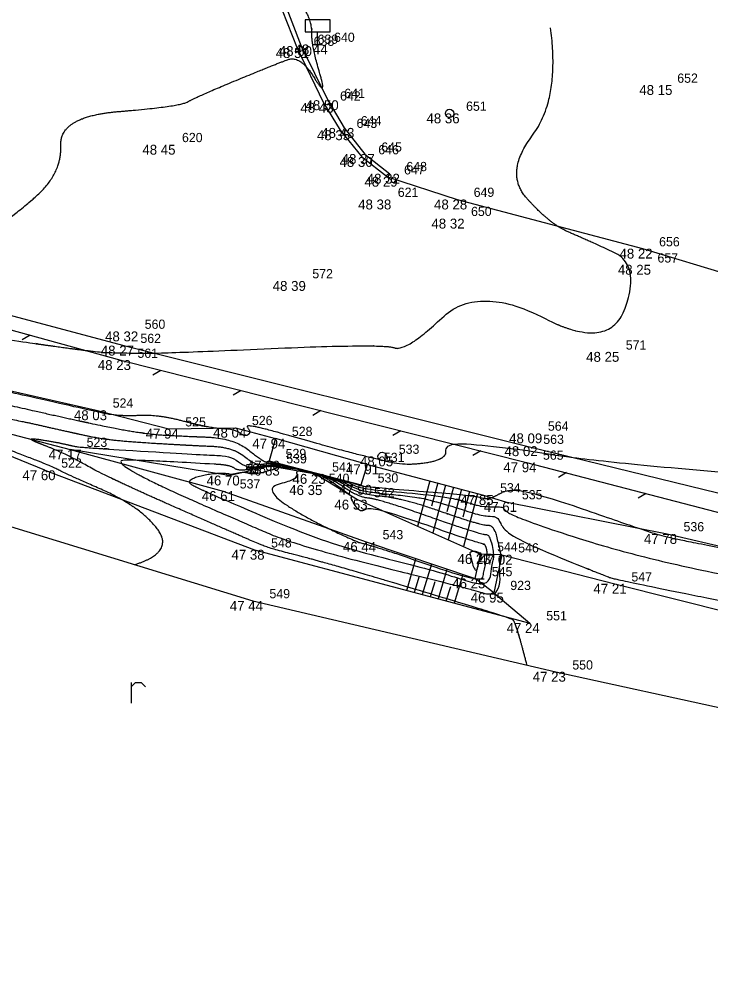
# Model space of a CAD drawing. Extents: x -704017 to -701500, y -1008977 to -1008450.
# Drawn here: x -703689.28 to -703668.32, y -1008728.25 to -1008699.18 of the extents above; entities that cross this region are included whole.
import ezdxf

# ---------------------------------------------------------------- set-up
doc = ezdxf.new("R2010")
doc.units = 0
for name, color, linetype in [('Z_bet_konstrukce', 7, 'Continuous'), ('Z_body', 7, 'Continuous'), ('Z_body_cisla', 7, 'Continuous'), ('Z_body_vysky', 7, 'Continuous'), ('Z_dopravni_znaceni', 7, 'Continuous'), ('Z_komunikace', 7, 'Continuous'), ('Z_obruby', 7, 'Continuous'), ('Z_popis', 7, 'Continuous'), ('Z_rozhrani_nezpevnene', 7, 'Continuous'), ('Z_site_znaky_plynovod', 7, 'Continuous'), ('Z_sloupky', 7, 'Continuous'), ('Z_svodidla', 7, 'Continuous'), ('Z_teren_hrany_paty', 7, 'Continuous'), ('Z_vrstevnice_hlavni', 7, 'Continuous'), ('Z_vrstevnice_vedlejsi', 7, 'Continuous')]:
    doc.layers.add(name, color=color, linetype=linetype)

# ---------------------------------------------------------------- blocks, each defined once
blk = doc.blocks.new('POINT_DISPLAY')
blk.add_line((0, 0), (0, 0))
blk = doc.blocks.new('Z529')
blk.add_line((0, 0), (0.2, 0.2))
blk = doc.blocks.new('Z301')
for p, q in [((-0.13, 0.38), (-0.13, -0.25)), ((-0.13, 0.25), (0, 0.38)), ((0, 0.38), (0.17, 0.38)), ((0.17, 0.38), (0.3, 0.25))]:
    blk.add_line(p, q)
blk = doc.blocks.new('Z526')
for p, q in [((0.38, 0.75), (-0.38, 0.75)), ((-0.38, 0.75), (-0.38, 0.38)), ((0.38, 0.38), (0.38, 0.75)), ((-0.38, 0.38), (0.38, 0.38)), ((0, 0), (0, 0.38)), ((-0.13, 0), (0.13, 0))]:
    blk.add_line(p, q)
blk = doc.blocks.new('Z15')
blk.add_circle((0, 0), 0.125)
blk = doc.blocks.new('Z614')
for p, q in [((-0.13, 0.03), (-0.1, 0.08)), ((-0.13, -0.03), (-0.13, 0.03)), ((-0.1, 0.08), (-0.08, 0.1)), ((-0.08, 0.1), (-0.03, 0.13)), ((-0.03, 0.13), (0.03, 0.13)), ((0.03, 0.13), (0.08, 0.1)), ((0.08, 0.1), (0.1, 0.08)), ((0.1, 0.08), (0.13, 0.03)), ((0.13, 0.03), (0.13, -0.03)), ((-0.1, -0.08), (-0.13, -0.03)), ((-0.08, -0.1), (-0.1, -0.08)), ((-0.03, -0.13), (-0.08, -0.1)), ((0.03, -0.13), (-0.03, -0.13)), ((0.08, -0.1), (0.03, -0.13)), ((0.1, -0.08), (0.08, -0.1)), ((0.13, -0.03), (0.1, -0.08))]:
    blk.add_line(p, q)

msp = doc.modelspace()

# ---------------------------------------------------------------- linework, layer by layer
at = {"layer": 'Z_bet_konstrukce'}
for p, q in [((-703681.52, -1008711.9), (-703681.71, -1008712.57)), ((-703678.73, -1008712.68), (-703681.52, -1008711.9)), ((-703681.71, -1008712.57), (-703678.92, -1008713.3)), ((-703678.92, -1008713.3), (-703678.73, -1008712.68))]:
    msp.add_line(p, q, dxfattribs=at)
at = {"layer": 'Z_komunikace'}
for p, q in [((-703681.66, -1008698.04), (-703680.86, -1008700.06)), ((-703680.86, -1008700.06), (-703680.06, -1008701.72)), ((-703680.06, -1008701.72), (-703679.56, -1008702.55)), ((-703679.56, -1008702.55), (-703678.9, -1008703.36)), ((-703678.9, -1008703.36), (-703678.12, -1008703.96)), ((-703678.12, -1008703.96), (-703676.01, -1008704.65)), ((-703676.01, -1008704.65), (-703670.39, -1008706.14)), ((-703670.39, -1008706.14), (-703661.94, -1008708.7)), ((-703694.9, -1008706.74), (-703686.11, -1008709.08)), ((-703686.11, -1008709.08), (-703673.9, -1008712.13)), ((-703673.9, -1008712.13), (-703663.52, -1008714.67))]:
    msp.add_line(p, q, dxfattribs=at)
at = {"layer": 'Z_obruby'}
for p, q in [((-703681.52, -1008697.96), (-703680.74, -1008700)), ((-703680.74, -1008700), (-703679.93, -1008701.64)), ((-703679.93, -1008701.64), (-703679.43, -1008702.48)), ((-703679.43, -1008702.48), (-703678.81, -1008703.27)), ((-703678.81, -1008703.27), (-703678.05, -1008703.87)), ((-703678.05, -1008703.87), (-703678.12, -1008703.96))]:
    msp.add_line(p, q, dxfattribs=at)
at = {"layer": 'Z_rozhrani_nezpevnene'}
for p, q in [((-703691.76, -1008713.89), (-703682.2, -1008716.82)), ((-703682.2, -1008716.82), (-703673.02, -1008718.97)), ((-703673.02, -1008718.97), (-703649.06, -1008724.21))]:
    msp.add_line(p, q, dxfattribs=at)
at = {"layer": 'Z_svodidla'}
for p, q in [((-703694.98, -1008707.1), (-703686.2, -1008709.52)), ((-703686.2, -1008709.52), (-703673.91, -1008712.62)), ((-703673.91, -1008712.62), (-703663.57, -1008715.31))]:
    msp.add_line(p, q, dxfattribs=at)
at = {"layer": 'Z_teren_hrany_paty'}
for p, q in [((-703693.42, -1008709.56), (-703686.95, -1008711.04)), ((-703693.92, -1008710.62), (-703687.74, -1008712.23)), ((-703688.51, -1008712.86), (-703693.92, -1008710.62)), ((-703686.95, -1008711.04), (-703684.75, -1008711.6)), ((-703684.75, -1008711.6), (-703682.73, -1008711.57)), ((-703682.73, -1008711.57), (-703681.52, -1008711.9)), ((-703687.74, -1008712.23), (-703683.1, -1008713.49)), ((-703682.93, -1008713.02), (-703687.74, -1008712.23)), ((-703682.93, -1008713.02), (-703681.69, -1008712.72)), ((-703681.69, -1008712.72), (-703680.3, -1008712.97)), ((-703678.73, -1008712.68), (-703675.21, -1008713.61)), ((-703688.51, -1008712.86), (-703682.15, -1008715.27)), ((-703680.3, -1008712.97), (-703679.03, -1008713.75)), ((-703676.84, -1008713.18), (-703677.21, -1008714.56)), ((-703676.6, -1008713.24), (-703676.79, -1008713.95)), ((-703676.36, -1008713.31), (-703676.75, -1008714.76)), ((-703683.1, -1008713.49), (-703678.77, -1008715.03)), ((-703676.12, -1008713.37), (-703676.32, -1008714.12)), ((-703675.88, -1008713.43), (-703676.28, -1008714.97)), ((-703675.64, -1008713.5), (-703675.84, -1008714.28)), ((-703675.39, -1008713.56), (-703675.82, -1008715.17)), ((-703675.21, -1008713.61), (-703674.55, -1008713.82)), ((-703679.03, -1008713.75), (-703675.3, -1008715.4)), ((-703674.55, -1008713.82), (-703669.65, -1008714.79)), ((-703669.65, -1008714.79), (-703648.46, -1008719.69)), ((-703678.77, -1008715.03), (-703675.46, -1008716.14)), ((-703682.15, -1008715.27), (-703673.81, -1008717.49)), ((-703675.46, -1008716.14), (-703675.3, -1008715.4)), ((-703674.66, -1008715.42), (-703675.3, -1008715.4)), ((-703677.54, -1008716.5), (-703677.26, -1008715.54)), ((-703674.66, -1008715.42), (-703674.9, -1008716.57)), ((-703674.66, -1008715.42), (-703671.23, -1008716.3)), ((-703677.06, -1008716.62), (-703676.78, -1008715.7)), ((-703676.58, -1008716.75), (-703676.31, -1008715.86)), ((-703677.3, -1008716.56), (-703677.16, -1008716.09)), ((-703676.82, -1008716.69), (-703676.68, -1008716.23)), ((-703676.09, -1008716.88), (-703675.83, -1008716.01)), ((-703674.9, -1008716.57), (-703675.46, -1008716.14)), ((-703676.34, -1008716.82), (-703676.2, -1008716.38)), ((-703671.23, -1008716.3), (-703648.67, -1008721.98)), ((-703674.9, -1008716.57), (-703673.81, -1008717.49))]:
    msp.add_line(p, q, dxfattribs=at)
at = {"layer": 'Z_vrstevnice_hlavni'}
for points in [[(-703662.375, -1008703.261), (-703663.705, -1008704.538), (-703663.066, -1008706.616), (-703661.034, -1008707.71), (-703652.649, -1008710.765), (-703650.692, -1008713.756), (-703662.914, -1008712.66), (-703663.337, -1008713.482), (-703663.459, -1008713.218), (-703665.771, -1008713.127), (-703672.17, -1008712.553), (-703673.902, -1008712.253), (-703676.453, -1008711.979), (-703676.294, -1008712.522), (-703677.513, -1008712.733), (-703678.441, -1008712.526), (-703679.753, -1008712.195), (-703682.488, -1008711.408), (-703682.246, -1008711.702), (-703682.439, -1008711.856), (-703682.736, -1008711.613), (-703683.538, -1008711.582), (-703685.05, -1008711.17), (-703686.217, -1008711.227), (-703686.978, -1008711.082), (-703693.222, -1008709.653), (-703693.449, -1008709.621), (-703696.433, -1008709.345), (-703698.144, -1008709.706)], [(-703683.37, -1008712.676), (-703682.885, -1008712.695), (-703682.625, -1008712.908), (-703681.693, -1008712.696), (-703680.95, -1008712.786), (-703679.664, -1008713.122), (-703678.992, -1008713.596), (-703677.67, -1008713.7), (-703675.257, -1008714.549), (-703674.882, -1008714.518), (-703674.676, -1008715.419), (-703674.681, -1008715.439), (-703674.729, -1008715.749), (-703674.712, -1008716.729), (-703675.743, -1008716.419), (-703680.784, -1008715.173), (-703682.619, -1008714.392), (-703685.231, -1008713.242), (-703686.331, -1008712.613), (-703686, -1008712.516), (-703683.37, -1008712.676)]]:
    msp.add_open_spline(points, degree=2, dxfattribs=at)
at = {"layer": 'Z_vrstevnice_vedlejsi'}
for points in [[(-703903.901, -1008677.414), (-703895.994, -1008675.935), (-703889.404, -1008675.668), (-703883.497, -1008675.709), (-703880.188, -1008675.348), (-703871.92, -1008674.519), (-703871.264, -1008674.488), (-703869.883, -1008674.411), (-703857.019, -1008674.18), (-703851.04, -1008674.21), (-703845.877, -1008674.639), (-703844.914, -1008674.732), (-703843.842, -1008674.839), (-703833.885, -1008676.193), (-703833.602, -1008676.214), (-703827.074, -1008676.454), (-703820.637, -1008677.013), (-703819.085, -1008677.479), (-703817.494, -1008677.708), (-703816.649, -1008677.812), (-703815.145, -1008678.799), (-703813.275, -1008679.054), (-703808.86, -1008680.311), (-703807.479, -1008679.952), (-703807.029, -1008679.932), (-703806.152, -1008679.075), (-703805.581, -1008678.971), (-703797.43, -1008679.786), (-703793.151, -1008680.113), (-703793.068, -1008680.19), (-703791.121, -1008680.56), (-703781.432, -1008681.982), (-703778.695, -1008682.405), (-703771.938, -1008683.858), (-703770.452, -1008684.278), (-703763.828, -1008685.759), (-703763.797, -1008685.768), (-703761.168, -1008686.558), (-703747.818, -1008690.4), (-703742.179, -1008692.485), (-703737.36, -1008694.393), (-703733.156, -1008695.929), (-703727.167, -1008698.103), (-703725.161, -1008698.789), (-703723.896, -1008699.212), (-703720.183, -1008700.697), (-703715.514, -1008702.276), (-703712.41, -1008702.891), (-703710.963, -1008702.88), (-703712.695, -1008701.493), (-703709.645, -1008702.135), (-703708.013, -1008702.153), (-703705.646, -1008702.274), (-703704.578, -1008701.603), (-703704.387, -1008701.057), (-703700.96, -1008699.93), (-703700.202, -1008700.451), (-703699.81, -1008700.652), (-703698.094, -1008698.58), (-703697.691, -1008698.623), (-703697.448, -1008698.667), (-703697.269, -1008698.752), (-703696.517, -1008698.604), (-703691.764, -1008698.535), (-703690.534, -1008698.099), (-703682.28, -1008696.05), (-703681.603, -1008697.7), (-703681.86, -1008696.66), (-703681.871, -1008694.534), (-703681.891, -1008694.375), (-703681.902, -1008694.348), (-703681.882, -1008694.278), (-703682.109, -1008690.719)], [(-703807.297, -1008680.919), (-703806.022, -1008679.671), (-703805.093, -1008679.503), (-703802.305, -1008679.782), (-703793.163, -1008680.481), (-703793.114, -1008680.526), (-703789.296, -1008681.251), (-703783.644, -1008682.081), (-703777.104, -1008683.093), (-703772.76, -1008684.026), (-703768.418, -1008685.255), (-703764.031, -1008686.236), (-703763.232, -1008686.458), (-703751.305, -1008690.045), (-703748.036, -1008691.082), (-703744.91, -1008692.192), (-703733.361, -1008696.411), (-703726.6, -1008698.866), (-703723.975, -1008699.841), (-703720.905, -1008701.411), (-703718.03, -1008702.753), (-703712.267, -1008704.53), (-703710.202, -1008704.791), (-703708.662, -1008704.906), (-703707.603, -1008704.793), (-703707.048, -1008704.993), (-703706.17, -1008704.973), (-703703.74, -1008705.265), (-703702.766, -1008705.456), (-703700.195, -1008705.706), (-703698.282, -1008705.979), (-703696.421, -1008706.348), (-703695.507, -1008706.084), (-703694.795, -1008706.478), (-703693.006, -1008705.814), (-703689.833, -1008705.247), (-703689.662, -1008705.32), (-703687.978, -1008703.873), (-703688.064, -1008702.126), (-703684.422, -1008701.833), (-703683.912, -1008701.534), (-703681.525, -1008700.548), (-703680.76, -1008700.268), (-703679.93, -1008701.64), (-703680.427, -1008699.969), (-703680.401, -1008699.283), (-703680.818, -1008698.558), (-703680.971, -1008698.507), (-703681.394, -1008697.409), (-703681.276, -1008696.992), (-703681.271, -1008696.439), (-703681.266, -1008694.476), (-703681.326, -1008694.152), (-703681.367, -1008693.463), (-703681.525, -1008690.986)], [(-703798.757, -1008680.422), (-703793.175, -1008680.848), (-703793.16, -1008680.862), (-703787.47, -1008681.943), (-703785.855, -1008682.18), (-703775.513, -1008683.78), (-703773.582, -1008684.195), (-703766.383, -1008686.232), (-703764.235, -1008686.712), (-703762.667, -1008687.148), (-703755.549, -1008689.289), (-703748.192, -1008691.622), (-703741.16, -1008694.119), (-703733.566, -1008696.894), (-703729.12, -1008698.508), (-703723.762, -1008700.498), (-703721.872, -1008701.464), (-703715.214, -1008704.572), (-703709.866, -1008706.221), (-703707.712, -1008706.639), (-703706.606, -1008706.329), (-703703.49, -1008707.357), (-703703.315, -1008707.639), (-703702.948, -1008707.636), (-703698.76, -1008708.615), (-703698.56, -1008708.691), (-703697.951, -1008708.744), (-703697.715, -1008708.694), (-703697.228, -1008708.739), (-703694.278, -1008708.207), (-703687.078, -1008709.278), (-703686.155, -1008709.3), (-703685.133, -1008709.324), (-703678.251, -1008709.016), (-703677.568, -1008709.276), (-703675.381, -1008707.211), (-703671.4, -1008709.27), (-703670.44, -1008706.63), (-703672.1, -1008705.867), (-703673.2, -1008705.395), (-703674.586, -1008703.849), (-703672.888, -1008701.59), (-703673.18, -1008699.44)], [(-703700.7, -1008711.12), (-703698.357, -1008710.719), (-703698.208, -1008710.769), (-703698.154, -1008710.63), (-703695.151, -1008709.995), (-703693.689, -1008710.131), (-703691.571, -1008710.429), (-703687.207, -1008711.427), (-703685.488, -1008711.755), (-703684.471, -1008711.818), (-703682.773, -1008711.884), (-703681.863, -1008712.626), (-703681.707, -1008712.591), (-703681.583, -1008712.606), (-703679.044, -1008713.27), (-703678.932, -1008713.349), (-703675.499, -1008713.621), (-703675.216, -1008713.72), (-703674.935, -1008713.698), (-703674.278, -1008713.311), (-703670.515, -1008714.619), (-703669.733, -1008714.869), (-703668.973, -1008715.022), (-703667.001, -1008715.403), (-703665.573, -1008715.453), (-703662.032, -1008715.678), (-703659.163, -1008716.177), (-703650.249, -1008717.873), (-703649.829, -1008717.937), (-703648.43, -1008718.027), (-703641.256, -1008718.604), (-703630.516, -1008719.414), (-703629.174, -1008719.566), (-703628.386, -1008719.543), (-703629.782, -1008717.057), (-703630.499, -1008716.157), (-703632.715, -1008715.365), (-703634.903, -1008713.707), (-703639.893, -1008710.897), (-703628.261, -1008712.566), (-703623.572, -1008715.13), (-703614.621, -1008717.569), (-703610.805, -1008718.458), (-703609.832, -1008718.61), (-703608.593, -1008718.831), (-703604.628, -1008718.918), (-703595.491, -1008719.164)], [(-703685.785, -1008715.721), (-703684.566, -1008715.335), (-703685.619, -1008713.955), (-703687.964, -1008712.924), (-703688.331, -1008712.713), (-703693.738, -1008710.667), (-703689.92, -1008711.205), (-703687.437, -1008711.773), (-703686.459, -1008711.96), (-703684.104, -1008712.104), (-703682.811, -1008712.154), (-703682.117, -1008712.72), (-703681.703, -1008712.626), (-703681.372, -1008712.666), (-703679.251, -1008713.221), (-703678.952, -1008713.431), (-703676.223, -1008713.647), (-703675.229, -1008713.997), (-703674.61, -1008713.946), (-703674.571, -1008714.118), (-703673.637, -1008714.502), (-703670.426, -1008715.532), (-703663.333, -1008716.955), (-703648.472, -1008719.823), (-703647.938, -1008719.874), (-703645.556, -1008720.323), (-703631.32, -1008722.36), (-703618.794, -1008723.782), (-703611.44, -1008723.57), (-703607.735, -1008721.567), (-703607.879, -1008720.984), (-703608.131, -1008720.883), (-703609.134, -1008720.506), (-703610.859, -1008719.621), (-703613.171, -1008718.885), (-703615.019, -1008718.218), (-703610.836, -1008719.192), (-703603.781, -1008720.296), (-703594.8, -1008721.903), (-703591.285, -1008721.98), (-703578.784, -1008723.173)], [(-703673.894, -1008718.765), (-703674.229, -1008717.457), (-703674.406, -1008717.331), (-703679.958, -1008715.663), (-703681.683, -1008715.237), (-703682.31, -1008714.969), (-703686.597, -1008713.083), (-703687.883, -1008712.347), (-703689.194, -1008711.851), (-703688.268, -1008711.982), (-703687.667, -1008712.119), (-703687.429, -1008712.165), (-703683.737, -1008712.39), (-703682.848, -1008712.425), (-703682.371, -1008712.814), (-703681.698, -1008712.661), (-703681.161, -1008712.726), (-703679.457, -1008713.172), (-703678.972, -1008713.514), (-703676.946, -1008713.674), (-703675.243, -1008714.273), (-703674.746, -1008714.232), (-703674.617, -1008714.796), (-703671.562, -1008716.052), (-703671.119, -1008716.194), (-703657.694, -1008718.888), (-703648.548, -1008720.652), (-703644.676, -1008721.021), (-703631.807, -1008723.449), (-703630.734, -1008723.7), (-703625.919, -1008724.662), (-703619.121, -1008725.828), (-703612.234, -1008727.005), (-703611.334, -1008727.151), (-703606.416, -1008727.92), (-703605.422, -1008728.07), (-703600.671, -1008728.039), (-703593.336, -1008728.232), (-703592.448, -1008728.228), (-703592.407, -1008728.229), (-703591.605, -1008728.268), (-703592.553, -1008726.04), (-703592.822, -1008724.951), (-703594.337, -1008724.346), (-703600.351, -1008722.084), (-703601.791, -1008721.346), (-703597.729, -1008721.982), (-703591.68, -1008723.064), (-703586.147, -1008724.273), (-703579.541, -1008725.645), (-703574.448, -1008726.131), (-703561.396, -1008727.415)], [(-703683.003, -1008712.963), (-703682.923, -1008712.966), (-703682.879, -1008713.001), (-703682.453, -1008712.905), (-703682.203, -1008713), (-703681.475, -1008712.818), (-703681.505, -1008712.753), (-703680.739, -1008712.845), (-703679.87, -1008713.073), (-703679.012, -1008713.678), (-703678.393, -1008713.727), (-703675.271, -1008714.825), (-703675.017, -1008714.805), (-703674.879, -1008715.413), (-703674.941, -1008715.672), (-703675.06, -1008716.447), (-703676.418, -1008715.966), (-703679.885, -1008715.109), (-703682.927, -1008713.814), (-703683.865, -1008713.401), (-703684.26, -1008713.175), (-703683.442, -1008712.936), (-703683.003, -1008712.963)], [(-703678.986, -1008715.045), (-703680.298, -1008714.486), (-703681.958, -1008713.414), (-703680.803, -1008713.126), (-703680.925, -1008712.858), (-703680.528, -1008712.905), (-703680.077, -1008713.023), (-703679.157, -1008713.672), (-703679.258, -1008713.677), (-703678.943, -1008714.177), (-703678.657, -1008713.915), (-703675.285, -1008715.102), (-703675.153, -1008715.091), (-703675.081, -1008715.407), (-703675.2, -1008715.906), (-703675.26, -1008716.294), (-703678.315, -1008715.211), (-703678.986, -1008715.045)], [(-703680.317, -1008713.027), (-703680.346, -1008712.962), (-703680.317, -1008712.965), (-703680.283, -1008712.974), (-703680.215, -1008713.022), (-703680.317, -1008713.027)], [(-703675.63, -1008715.365), (-703675.549, -1008715.29), (-703675.299, -1008715.378), (-703675.289, -1008715.377), (-703675.284, -1008715.401), (-703675.46, -1008716.14), (-703675.63, -1008715.365)]]:
    msp.add_open_spline(points, degree=2, dxfattribs=at)

# ---------------------------------------------------------------- block references
at = {"layer": 'Z_body'}
for p in [(-703680.24, -1008699.95), (-703680.86, -1008700.06), (-703680.74, -1008700), (-703669.84, -1008701.18), (-703680.06, -1008701.72), (-703679.93, -1008701.64), (-703676.24, -1008702.04), (-703679.56, -1008702.55), (-703679.43, -1008702.48), (-703684.85, -1008702.99), (-703678.9, -1008703.36), (-703678.81, -1008703.27), (-703678.12, -1008703.96), (-703678.05, -1008703.87), (-703678.31, -1008704.65), (-703676.01, -1008704.65), (-703676.09, -1008705.23), (-703670.39, -1008706.14), (-703670.44, -1008706.63), (-703680.9, -1008707.12), (-703685.98, -1008708.65), (-703686.11, -1008709.08), (-703671.4, -1008709.27), (-703686.2, -1008709.52), (-703686.95, -1008711.04), (-703684.75, -1008711.6), (-703682.73, -1008711.57), (-703681.52, -1008711.9), (-703673.76, -1008711.74), (-703673.9, -1008712.13), (-703687.74, -1008712.23), (-703678.28, -1008712.44), (-703681.71, -1008712.57), (-703681.69, -1008712.72), (-703678.73, -1008712.68), (-703673.91, -1008712.62), (-703688.51, -1008712.86), (-703682.93, -1008713.02), (-703680.3, -1008712.97), (-703680.4, -1008713.31), (-703678.92, -1008713.3), (-703683.1, -1008713.49), (-703675.21, -1008713.61), (-703679.03, -1008713.75), (-703674.55, -1008713.82), (-703669.65, -1008714.79), (-703678.77, -1008715.03), (-703682.15, -1008715.27), (-703675.3, -1008715.4), (-703674.66, -1008715.42), (-703675.46, -1008716.14), (-703671.23, -1008716.3), (-703682.2, -1008716.82), (-703674.9, -1008716.57), (-703673.81, -1008717.49), (-703673.02, -1008718.97)]:
    msp.add_blockref('POINT_DISPLAY', p, dxfattribs=at)
at = {"layer": 'Z_dopravni_znaceni'}
msp.add_blockref('Z526', (-703680.24, -1008699.95), dxfattribs=at)
at = {"layer": 'Z_popis'}
msp.add_blockref('Z301', (-703685.76, -1008719.67), dxfattribs=at)
at = {"layer": 'Z_site_znaky_plynovod', "rotation": 10.799999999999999}
msp.add_blockref('Z614', (-703678.28, -1008712.44), dxfattribs=at)
at = {"layer": 'Z_sloupky'}
msp.add_blockref('Z15', (-703676.24, -1008702.04), dxfattribs=at)
at = {"layer": 'Z_svodidla'}
for p, rotation in [((-703688.95, -1008708.76), 164.6), ((-703684.99, -1008709.83), 165.8), ((-703682.56, -1008710.44), 165.8), ((-703680.14, -1008711.05), 165.8), ((-703677.72, -1008711.66), 165.8), ((-703675.29, -1008712.27), 165.8), ((-703672.7, -1008712.93), 165.4), ((-703670.28, -1008713.56), 165.4)]:
    msp.add_blockref('Z529', p, dxfattribs=dict(at, rotation=rotation))

# ---------------------------------------------------------------- texts
at = {"layer": 'Z_body_cisla'}
for s, p in [('638', (-703680.36, -1008699.99)), ('639', (-703680.24, -1008699.93)), ('640', (-703679.74, -1008699.87)), ('652', (-703669.34, -1008701.11)), ('642', (-703679.56, -1008701.65)), ('641', (-703679.43, -1008701.57)), ('651', (-703675.74, -1008701.96)), ('643', (-703679.06, -1008702.48)), ('644', (-703678.93, -1008702.4)), ('620', (-703684.35, -1008702.91)), ('646', (-703678.4, -1008703.28)), ('645', (-703678.31, -1008703.2)), ('647', (-703677.62, -1008703.89)), ('648', (-703677.55, -1008703.79)), ('621', (-703677.81, -1008704.57)), ('649', (-703675.51, -1008704.57)), ('650', (-703675.59, -1008705.15)), ('656', (-703669.89, -1008706.07)), ('657', (-703669.94, -1008706.56)), ('572', (-703680.4, -1008707.04)), ('560', (-703685.48, -1008708.57)), ('562', (-703685.61, -1008709)), ('571', (-703670.9, -1008709.2)), ('561', (-703685.7, -1008709.45)), ('524', (-703686.45, -1008710.96)), ('525', (-703684.25, -1008711.53)), ('526', (-703682.23, -1008711.49)), ('528', (-703681.02, -1008711.82)), ('564', (-703673.26, -1008711.66)), ('523', (-703687.24, -1008712.15)), ('563', (-703673.4, -1008712.06)), ('533', (-703677.78, -1008712.36)), ('522', (-703688.01, -1008712.78)), ('529', (-703681.21, -1008712.49)), ('539', (-703681.19, -1008712.65)), ('531', (-703678.23, -1008712.61)), ('565', (-703673.41, -1008712.54)), ('538', (-703682.43, -1008712.95)), ('541', (-703679.8, -1008712.9)), ('540', (-703679.9, -1008713.24)), ('530', (-703678.42, -1008713.23)), ('537', (-703682.6, -1008713.41)), ('534', (-703674.71, -1008713.53)), ('542', (-703678.53, -1008713.68)), ('535', (-703674.05, -1008713.74)), ('536', (-703669.15, -1008714.71)), ('543', (-703678.27, -1008714.95)), ('548', (-703681.65, -1008715.2)), ('544', (-703674.8, -1008715.32)), ('546', (-703674.16, -1008715.35)), ('545', (-703674.96, -1008716.07)), ('547', (-703670.73, -1008716.23)), ('923', (-703674.4, -1008716.49)), ('549', (-703681.7, -1008716.74)), ('551', (-703673.31, -1008717.41)), ('550', (-703672.52, -1008718.9))]:
    msp.add_text(s, height=0.28, dxfattribs=at).set_placement(p)
at = {"layer": 'Z_body_vysky'}
for s, p in [('48 60', (-703681.415, -1008700.3)), ('48 44', (-703680.94, -1008700.25)), ('48 51', (-703681.51, -1008700.36)), ('48 15', (-703670.49, -1008701.48)), ('48 43', (-703680.76, -1008702.02)), ('48 50', (-703680.605, -1008701.94)), ('48 36', (-703676.94, -1008702.34)), ('48 35', (-703680.26, -1008702.85)), ('48 43', (-703680.13, -1008702.78)), ('48 45', (-703685.55, -1008703.29)), ('48 30', (-703679.575, -1008703.66)), ('48 37', (-703679.51, -1008703.57)), ('48 29', (-703678.82, -1008704.26)), ('48 32', (-703678.75, -1008704.17)), ('48 38', (-703679.01, -1008704.95)), ('48 28', (-703676.71, -1008704.95)), ('48 32', (-703676.79, -1008705.53)), ('48 22', (-703671.09, -1008706.44)), ('48 25', (-703671.14, -1008706.93)), ('48 39', (-703681.6, -1008707.42)), ('48 32', (-703686.68, -1008708.95)), ('48 27', (-703686.81, -1008709.38)), ('48 25', (-703672.1, -1008709.57)), ('48 23', (-703686.9, -1008709.82)), ('48 03', (-703687.625, -1008711.34)), ('47 94', (-703685.45, -1008711.9)), ('48 04', (-703683.405, -1008711.87)), ('47 94', (-703682.22, -1008712.2)), ('48 09', (-703674.435, -1008712.04)), ('48 02', (-703674.575, -1008712.43)), ('47 17', (-703688.39, -1008712.53)), ('48 05', (-703678.955, -1008712.74)), ('46 83', (-703682.39, -1008713.02)), ('47 90', (-703682.385, -1008712.87)), ('47 91', (-703679.38, -1008712.98)), ('47 94', (-703674.61, -1008712.92)), ('47 60', (-703689.185, -1008713.16)), ('46 70', (-703683.605, -1008713.32)), ('46 23', (-703681, -1008713.27)), ('46 35', (-703681.1, -1008713.61)), ('47 90', (-703679.595, -1008713.6)), ('46 61', (-703683.75, -1008713.79)), ('47 85', (-703675.91, -1008713.91)), ('46 53', (-703679.73, -1008714.05)), ('47 61', (-703675.2, -1008714.12)), ('47 78', (-703670.35, -1008715.09)), ('46 44', (-703679.47, -1008715.33)), ('47 38', (-703682.85, -1008715.57)), ('46 23', (-703676, -1008715.7)), ('47 02', (-703675.335, -1008715.72)), ('46 25', (-703676.16, -1008716.44)), ('47 21', (-703671.88, -1008716.6)), ('47 44', (-703682.9, -1008717.12)), ('46 95', (-703675.6, -1008716.87)), ('47 24', (-703674.51, -1008717.79)), ('47 23', (-703673.72, -1008719.27))]:
    msp.add_text(s, height=0.3, dxfattribs=at).set_placement(p)

doc.saveas('drawing.dxf')
